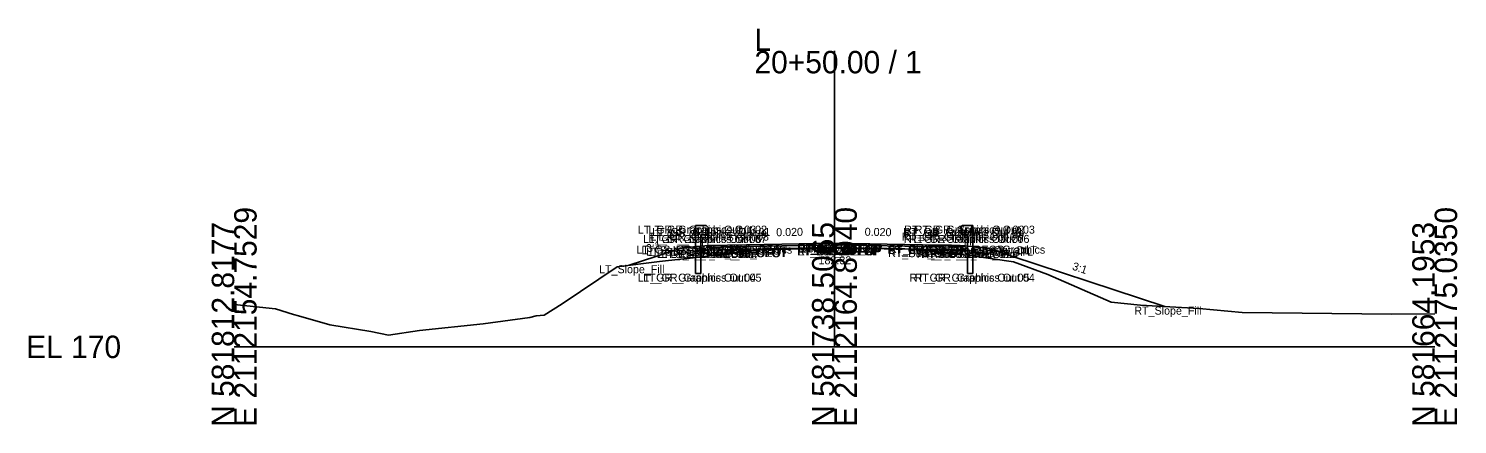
# Model space of a CAD drawing. Extents: x -26 to 3453, y -333 to 9539.
# Drawn here: x 974.3 to 1152.8, y 1490.3 to 1539.8 of the extents above; entities that cross this region are included whole.
import ezdxf

# ---------------------------------------------------------------- set-up
doc = ezdxf.new("R2010")
doc.units = 0
for name, color, linetype in [('Default', 7, 'Continuous'), ('Exist Cross Section Cell', 7, 'Continuous'), ('Exist XS Center Line Elevation Label', 7, 'Continuous'), ('Exist XS Ground Line', 7, 'Continuous'), ('Prop CMT Guardrail Graphics', 7, 'Continuous'), ('Prop CMT Pvmt Course 1', 7, 'Continuous'), ('Prop CMT Pvmt Course 2', 7, 'Continuous'), ('Prop CMT Pvmt Course 3', 7, 'Continuous'), ('Prop CMT Pvmt Surface', 7, 'Continuous'), ('Prop CMT Pvmt Surface Shoulder', 7, 'Continuous'), ('Prop CMT Shld Paved Course 1', 7, 'Continuous'), ('Prop CMT Shld Paved Course 2', 7, 'Continuous'), ('Prop CMT Shld Paved Course 3', 7, 'Continuous'), ('Prop CMT Slope Grass', 7, 'Continuous'), ('Prop CMT Subgrade Earthwork', 7, 'Continuous'), ('Prop XS SE Text', 7, 'Continuous'), ('Prop XS Side Slope Text', 7, 'Continuous'), ('Scratch_Level_0', 7, 'Continuous')]:
    doc.layers.add(name, color=color, linetype=linetype)

msp = doc.modelspace()

# ---------------------------------------------------------------- linework, layer by layer
at = {"layer": 'Exist Cross Section Cell'}
for p, q in [((1075, 1500), (1075, 1536.98)), ((1000, 1500), (1075, 1500)), ((1075, 1500), (1150, 1500))]:
    msp.add_line(p, q, dxfattribs=at)
at = {"layer": 'Exist XS Ground Line'}
for p, q in [((1067.82, 1512.15), (1074.8, 1512.33)), ((1074.8, 1512.33), (1077.65, 1512.28)), ((1077.65, 1512.28), (1084.77, 1512.2)), ((1084.77, 1512.2), (1088.79, 1511.79)), ((1047.84, 1510), (1053.16, 1510.68)), ((1053.16, 1510.68), (1058.11, 1511.21)), ((1058.11, 1511.21), (1065.16, 1512.09)), ((1065.16, 1512.09), (1067.82, 1512.15)), ((1088.79, 1511.79), (1092.19, 1511.37)), ((1092.19, 1511.37), (1097.38, 1510.62)), ((1097.38, 1510.62), (1101.65, 1509.04)), ((1040.99, 1505.38), (1047.84, 1510)), ((1101.65, 1509.04), (1109.57, 1505.6)), ((1000, 1505.3), (1005.15, 1504.74)), ((1038.72, 1503.97), (1040.99, 1505.38)), ((1109.57, 1505.6), (1113.26, 1505.2)), ((1113.26, 1505.2), (1120.59, 1504.79)), ((1005.15, 1504.74), (1007.42, 1504.05)), ((1007.42, 1504.05), (1008.03, 1503.89)), ((1008.03, 1503.89), (1011.95, 1502.75)), ((1031.11, 1502.88), (1036.95, 1503.68)), ((1036.95, 1503.68), (1037.74, 1503.86)), ((1037.74, 1503.86), (1038.72, 1503.97)), ((1120.59, 1504.79), (1125.96, 1504.3)), ((1125.96, 1504.3), (1144.66, 1504.1)), ((1144.66, 1504.1), (1150, 1504.13)), ((1011.95, 1502.75), (1017.07, 1501.94)), ((1017.07, 1501.94), (1019.29, 1501.47)), ((1019.29, 1501.47), (1023.14, 1502.04)), ((1023.14, 1502.04), (1031.11, 1502.88))]:
    msp.add_line(p, q, dxfattribs=at)
at = {"layer": 'Prop CMT Guardrail Graphics'}
for points in [[(1057.65, 1509.15), (1057.65, 1515.15)], [(1057.65, 1515.15), (1058.98, 1515.15), (1059.25, 1514.86)], [(1059.25, 1514.28), (1058.98, 1513.98), (1058.31, 1513.98)], [(1058.31, 1513.98), (1058.31, 1509.15)], [(1059.25, 1514.86), (1058.98, 1514.57)], [(1058.98, 1514.57), (1059.25, 1514.28)], [(1092.31, 1515.15), (1090.97, 1515.15), (1090.7, 1514.86)], [(1090.7, 1514.86), (1090.97, 1514.57)], [(1090.97, 1514.57), (1090.7, 1514.28)], [(1090.7, 1514.28), (1090.97, 1513.99), (1091.64, 1513.99)], [(1091.64, 1513.99), (1091.64, 1509.15)], [(1092.31, 1509.15), (1092.31, 1515.15)], [(1058.31, 1509.15), (1057.65, 1509.15)], [(1091.64, 1509.15), (1092.31, 1509.15)]]:
    msp.add_lwpolyline(points, dxfattribs=at)
at = {"layer": 'Prop CMT Pvmt Course 1'}
for points in [[(1075, 1512.97), (1064, 1512.75)], [(1064, 1512.54), (1075, 1512.76)], [(1064, 1512.75), (1064, 1512.54)], [(1075, 1512.76), (1075, 1512.97)], [(1075, 1512.97), (1086, 1512.75)], [(1075, 1512.76), (1075, 1512.97)], [(1086, 1512.54), (1075, 1512.76)], [(1086, 1512.75), (1086, 1512.54)]]:
    msp.add_lwpolyline(points, dxfattribs=at)
msp.add_lwpolyline([(1075, 1512.76), (1075, 1512.84), (1075, 1512.84), (1075, 1512.76)], close=True, dxfattribs=at)
msp.add_lwpolyline([(1075, 1512.76), (1075, 1512.84), (1075, 1512.84), (1075, 1512.76)], close=True, dxfattribs=at)
at = {"layer": 'Prop CMT Pvmt Course 2'}
for points in [[(1075, 1512.76), (1064, 1512.54)], [(1064, 1512.54), (1064, 1512.21)], [(1064, 1512.21), (1075, 1512.43)], [(1075, 1512.43), (1075, 1512.76)], [(1075, 1512.43), (1075, 1512.76)], [(1075, 1512.76), (1086, 1512.54)], [(1086, 1512.21), (1075, 1512.43)], [(1086, 1512.54), (1086, 1512.21)]]:
    msp.add_lwpolyline(points, dxfattribs=at)
at = {"layer": 'Prop CMT Pvmt Course 3'}
for points in [[(1075, 1512.43), (1064, 1512.21)], [(1064, 1512.21), (1075, 1512.43)], [(1064, 1512.21), (1064, 1512.21)], [(1075, 1512.43), (1075, 1512.43)], [(1075, 1512.43), (1086, 1512.21)], [(1086, 1512.21), (1075, 1512.43)], [(1075, 1512.43), (1075, 1512.43)], [(1086, 1512.21), (1086, 1512.21)]]:
    msp.add_lwpolyline(points, dxfattribs=at)
at = {"layer": 'Prop CMT Pvmt Surface'}
for points in [[(1075, 1512.97), (1064, 1512.75)], [(1075, 1512.97), (1086, 1512.75)]]:
    msp.add_lwpolyline(points, dxfattribs=at)
at = {"layer": 'Prop CMT Pvmt Surface Shoulder'}
for points in [[(1064, 1512.75), (1059.26, 1512.65)], [(1086, 1512.75), (1090.69, 1512.65)]]:
    msp.add_lwpolyline(points, dxfattribs=at)
at = {"layer": 'Prop CMT Shld Paved Course 1'}
for points in [[(1064, 1512.75), (1059.26, 1512.65), (1059.05, 1512.44)], [(1059.05, 1512.44), (1064, 1512.54)], [(1064, 1512.54), (1064, 1512.75)], [(1086, 1512.75), (1090.69, 1512.65), (1090.9, 1512.44)], [(1086, 1512.54), (1086, 1512.75)], [(1090.9, 1512.44), (1086, 1512.54)]]:
    msp.add_lwpolyline(points, dxfattribs=at)
at = {"layer": 'Prop CMT Shld Paved Course 2'}
for points in [[(1064, 1512.54), (1059.05, 1512.44), (1058.71, 1512.1)], [(1058.71, 1512.1), (1064, 1512.21)], [(1064, 1512.21), (1064, 1512.54)], [(1086, 1512.54), (1090.9, 1512.44), (1091.24, 1512.1)], [(1086, 1512.21), (1086, 1512.54)], [(1091.24, 1512.1), (1086, 1512.21)]]:
    msp.add_lwpolyline(points, dxfattribs=at)
at = {"layer": 'Prop CMT Shld Paved Course 3'}
for points in [[(1064, 1512.21), (1058.71, 1512.1)], [(1058.71, 1512.1), (1064, 1512.21)], [(1064, 1512.21), (1064, 1512.21)], [(1086, 1512.21), (1091.24, 1512.1)], [(1091.24, 1512.1), (1086, 1512.21)], [(1086, 1512.21), (1086, 1512.21)], [(1058.71, 1512.1), (1058.71, 1512.1), (1058.71, 1512.1)], [(1091.24, 1512.1), (1091.24, 1512.1), (1091.24, 1512.1)]]:
    msp.add_lwpolyline(points, dxfattribs=at)
at = {"layer": 'Prop CMT Slope Grass'}
for points in [[(1056, 1512.39), (1049.35, 1510.2)], [(1059.25, 1512.65), (1056, 1512.39)], [(1059.26, 1512.65), (1059.25, 1512.65)], [(1090.69, 1512.65), (1090.7, 1512.65)], [(1090.7, 1512.65), (1094, 1512.39)], [(1094, 1512.39), (1116.29, 1505.03)]]:
    msp.add_lwpolyline(points, dxfattribs=at)
at = {"layer": 'Prop CMT Subgrade Earthwork'}
for points in [[(1058.71, 1512.1), (1058.24, 1512.57)], [(1064, 1512.21), (1058.71, 1512.1)], [(1075, 1512.43), (1064, 1512.21)], [(1075, 1512.43), (1086, 1512.21)], [(1086, 1512.21), (1091.24, 1512.1)], [(1091.24, 1512.1), (1091.72, 1512.57)]]:
    msp.add_lwpolyline(points, dxfattribs=at)

# ---------------------------------------------------------------- texts
at = {"layer": 'Default'}
msp.add_text('-', height=0.0001, dxfattribs=at).set_placement((1000, 1500))
at = {"layer": 'Exist Cross Section Cell'}
for s, p in [('L', (1065, 1536.98)), ('20+50.00 / 1', (1065, 1534.18)), ('EL 170', (974, 1498.6))]:
    msp.add_text(s, height=2.8, dxfattribs=at).set_placement(p)
for s, p in [('E 2112154.7529', (1002.8, 1490)), ('E 2112164.8940', (1077.8, 1490)), ('E 2112175.0350', (1152.8, 1490)), ('N 581812.8177', (1000, 1490)), ('N 581738.5065', (1075, 1490)), ('N 581664.1953', (1150, 1490))]:
    msp.add_text(s, height=2.8, rotation=90, dxfattribs=at).set_placement(p)
at = {"layer": 'Exist XS Center Line Elevation Label'}
msp.add_text('182.32', height=1, dxfattribs=at).set_placement((1073.01, 1510.32))
at = {"layer": 'Prop XS SE Text'}
for rotation, p in [(1.1458, (1067.73, 1513.82)), (358.8542, (1078.77, 1513.89))]:
    msp.add_text('0.020', height=1, rotation=rotation, dxfattribs=at).set_placement(p)
at = {"layer": 'Prop XS Side Slope Text'}
for rotation, p in [(18.2629, (1051.69, 1511.76)), (341.7371, (1104.63, 1509.67))]:
    msp.add_text('3:1', height=1, rotation=rotation, dxfattribs=at).set_placement(p)
at = {"layer": 'Scratch_Level_0'}
for s, p in [('LT_GR_Graphics Out 03', (1050.43, 1514.15)), ('LT_GR_Graphics Out 06', (1051.09, 1512.98)), ('LT_GR_Graphics Out 07', (1051.74, 1512.98)), ('LT_GR_Graphics Out 09', (1051.76, 1513.57)), ('LT_GR_Graphics Out 02', (1051.78, 1514.15)), ('LT_GR_Graphics Out 08', (1052.02, 1513.28)), ('LT_GR_Graphics Out 01', (1052.2, 1513.86)), ('RT_GR_Graphics Out 08', (1083.41, 1513.28)), ('RT_GR_Graphics Out 01', (1083.59, 1513.86)), ('RT_GR_Graphics Out 07', (1083.67, 1512.99)), ('RT_GR_Graphics Out 09', (1083.69, 1513.57)), ('RT_GR_Graphics Out 02', (1083.72, 1514.15)), ('RT_GR_Graphics Out 06', (1084.35, 1512.99)), ('RT_GR_Graphics Out 03', (1085.03, 1514.15)), ('LT_GS_OS_GR_Face_Graphics', (1050.25, 1511.65)), ('LT_Sub_Trench_Out_DLT', (1050.89, 1511.57)), ('LT_GS_OS_CTL', (1051.46, 1511.39)), ('LT_PS2_OEOP', (1054.84, 1511.44)), ('LT_PS1_OEOP', (1055.17, 1511.65)), ('LT_PV2_OEOT', (1059.75, 1511.54)), ('LT_PV3_OEOT', (1059.75, 1511.21)), ('LT_Sub_OEOT', (1059.77, 1511.21)), ('LT_PV1_OEOT', (1059.87, 1511.75)), ('RT_PV2_OEEOP', (1070.33, 1511.76)), ('RT_PV3_OEEOP', (1070.33, 1511.43)), ('RT_Sub_OEEOP', (1070.36, 1511.43)), ('LT_PV2_OEEOP', (1070.39, 1511.76)), ('LT_PV3_OEEOP', (1070.39, 1511.43)), ('LT_Sub_OEEOP', (1070.42, 1511.43)), ('RT_PV1_OEEOP', (1070.45, 1511.84)), ('LT_PV1_OEEOP', (1070.51, 1511.84)), ('RT_PV2_IEEOP', (1070.71, 1511.76)), ('LT_PV2_IEEOP', (1070.77, 1511.76)), ('RT_PV1_IEEOP', (1070.83, 1511.84)), ('LT_PV1_IEEOP', (1070.89, 1511.84)), ('PV2_PGL', (1072.35, 1511.76)), ('PV1_PGL', (1072.47, 1511.97)), ('RT_GS_OS_GR_Face_Graphics', (1081.64, 1511.65)), ('RT_PV2_OEOT', (1081.69, 1511.54)), ('RT_PV3_OEOT', (1081.69, 1511.21)), ('RT_Sub_OEOT', (1081.71, 1511.21)), ('RT_PV1_OEOT', (1081.81, 1511.75)), ('RT_Sub_Trench_Out_DLT', (1084.31, 1511.57)), ('RT_PS1_OEOP', (1086.54, 1511.65)), ('RT_PS2_OEOP', (1086.63, 1511.44)), ('RT_GS_OS_CTL', (1089.4, 1511.39)), ('LT_Sub_Trench_Out', (1052.82, 1511.1)), ('LT_PS3_Shelf_Out', (1053.37, 1511.1)), ('LT_PS3_OEOP', (1054.5, 1511.1)), ('RT_Sub_Trench_Out', (1085.29, 1511.1)), ('RT_PS3_Shelf_Out', (1085.84, 1511.1)), ('RT_PS3_OEOP', (1086.97, 1511.1)), ('LT_Slope_Fill', (1045.59, 1509.2)), ('LT_GR_Graphics Out 04', (1050.42, 1508.15)), ('LT_GR_Graphics Out 05', (1051.09, 1508.15)), ('RT_GR_Graphics Out 05', (1084.36, 1508.15)), ('RT_GR_Graphics Out 04', (1085.02, 1508.15)), ('RT_Slope_Fill', (1112.47, 1504.03))]:
    msp.add_text(s, height=1, dxfattribs=at).set_placement(p)

doc.saveas('drawing.dxf')
